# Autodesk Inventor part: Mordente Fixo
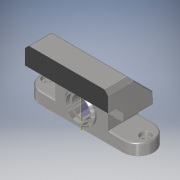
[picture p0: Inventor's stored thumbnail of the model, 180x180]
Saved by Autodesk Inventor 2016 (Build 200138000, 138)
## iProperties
Created: 2016-02
Part Number: Mordente Fixo
Material: Steel, Cast
Document SubType Name: Modeling
Designer: Vertex
Mass: 2584.79 g
Surface Area: 444.62 cm^2
Volume: 329.273 cm^3
Density: 7.85 g/cm^3
Appearance: Semi-Polished
Title: Apoio
Author: Vertex
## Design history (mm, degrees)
sketch "Sketch1"
  geometry: L1 (75, 80)-(25, 80); L2 (0, 15)-(0, 0); L3 (0, 15)-(40, 15); L4 (40, 35)-(40, 15); L5 (20, 35)-(40, 35); L6 (20, 75)-(20, 35); L7 (20, 75)-(25, 80); L8 (75, 80)-(125, 80); L9 (150, 15)-(150, 0); L10 (150, 15)-(110, 15); L11 (110, 35)-(110, 15); L12 (130, 35)-(110, 35); L13 (130, 75)-(130, 35); L14 (130, 75)-(125, 80); L15 (0, 0)-(150, 0); L16 (75, 50.194)-(75, -5); 5 further points
  constraints: 32 end point, 6 point on line, 2 parallel, 1 horizontal, 1 vertical
  dimensions: "d3" = 40 distance between parallel lines of L2 L4; "d5" = 5 distance of L6.start point (20, 80); "d6" = 5 distance of L1.end point (20, 80) (= d5); "d7" = 150 distance of L9.end L2.end; "d8" = 130 distance of point (140, 15) point (10, 15); "d9" = 20 distance between parallel lines of L12 L10; "d10" = 45 distance from line of L8 L12.start; "d67" = 15 distance of L9.end L9.start; "d68" = 45 vertical distance of L5.start L1.end
extrude "Extrusion1" new body sketch "Sketch1" stored distance "d11" = 40; taper "d12" = 0 deg
hole "Hole1" diameter "d15" = 26; stored, may be unused: countersink angle "d19" = 90 deg, drill point angle "d21" = 118 deg; dims "d13" = 75, "d14" = 25, "d16" = 7.5, "d17" = 3.75, "d18" = 2.5, "d20" = 30
hole "Hole2" diameter "d24" = 8; stored, may be unused: countersink angle "d28" = 90 deg, drill point angle "d30" = 118 deg; dims "d22" = 10, "d23" = 20, "d25" = 7.5, "d26" = 13.5, "d27" = 5, "d29" = 10
workplane "Work Plane1"
mirror "Mirror1"
sketch "Sketch2"
  geometry: C1 r 20 at (75, 25); C2 r 16 at (75, 25); 2 further points
  constraints: 2 centre point, 2 coincident
  dimensions: "d34" = 40 diameter of C1; "d40" = 32 diameter of C2
extrude "Extrusion2" join sketch "Sketch2" distance "d35" = 5; taper "d36" = 0 deg
chamfer "Chamfer3" distance "d41" = 2.5; stored, may be unused: second distance "d42" = 1.25, angle "d43" = 45 deg
fillet "Fillet6" dims "d66" = 0.5
chamfer "Chamfer4" distance "d69" = 30; stored, may be unused: second distance "d70" = 1.25, angle "d71" = 45 deg
fillet "Fillet8"
fillet "Fillet9"
fillet "Fillet10" dims "d72" = 2
sketch "Sketch3"
  geometry: L1 (22, 35)-(40, 35) reference; L2 (40, 35)-(40, 13) reference; L3 (20, 13)-(40, 13) reference; L4 (20, 0)-(20, 13) reference; L5 (20, 0)-(130, 0) reference; L6 (130, 13)-(130, 0) reference; L7 (110, 13)-(130, 13) reference; L8 (110, 35)-(110, 13) reference; L9 (110, 35)-(128, 35) reference; L10 (130, 37)-(130, 74.172) reference; L11 (129.414, 75.586)-(125.586, 79.414) reference; L12 (124.172, 80)-(25.828, 80) reference; L13 (24.414, 79.414)-(20.586, 75.586) reference; L14 (20, 74.172)-(20, 37) reference; L15 (20, 74.172)-(20, 37) reference; L16 (20, 55)-(130, 55); L17 (130, 37)-(130, 74.172) reference; C1 r 20 at (75, 25) reference; A1 r 2 centre (22, 37) between (20, 37) and (22, 35) reference; A2 r 2 centre (128, 37) between (128, 35) and (130, 37) reference; A3 r 2 centre (128, 74.172) between (130, 74.172) and (129.414, 75.586) reference; A4 r 2 centre (124.172, 78) between (125.586, 79.414) and (124.172, 80) reference; A5 r 2 centre (25.828, 78) between (25.828, 80) and (24.414, 79.414) reference; A6 r 2 centre (22, 74.172) between (20.586, 75.586) and (20, 74.172) reference; 1 further point
  constraints: 2 end point, 2 point on line, 1 perpendicular
extrude "Extrusion3" join sketch "Sketch3" distance "d73" = 20; taper "d74" = 0 deg
chamfer "Chamfer5" distance "d75" = 10; stored, may be unused: second distance "d76" = 1.25, angle "d77" = 45 deg
hole "Hole5" diameter "d80" = 4.92; stored, may be unused: countersink angle "d84" = 90 deg, drill point angle "d86" = 118 deg; dims "d78" = 10, "d79" = 10, "d81" = 12, "d82" = 3.75, "d83" = 2.5, "d85" = 20
mirror "Mirror6"
mirror "Mirror7"
body "Solid1"
node "Projected Loop1"
